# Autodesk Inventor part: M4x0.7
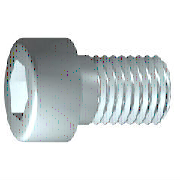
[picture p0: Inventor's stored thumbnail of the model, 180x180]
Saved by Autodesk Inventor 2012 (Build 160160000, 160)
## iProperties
Created: 2009-02
Part Number: M4x0.7
Material: 강, 연강
Description: 6각머리 태핑 나사
Document SubType Name: Modeling
Standard: KS B 1003
Standards Organization: KS
Language: ko-KR
Size Designation: M 4 x 12
Categories: <MemberInstance><Categories><Category DisplayName="조임쇠" InternalName="e4da775c-781d-43d5-af7c-5136215cf5a6" Mnemonic="FSTN"><Category DisplayName="볼트" InternalN
Density: 1 g/cm^3
Checked By: KYOUNG IL JANG
Vendor: CBT Solutions
Designer: KYOUNG IL JANG
Manager: KYOUNG IL JANG
Company: 한국ATC센터
IsCustomPart: 0
Author: KYOUNG IL JANG
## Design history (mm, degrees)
revolve "본체" stored, may be unused: angle "d10" = 90 deg
sketch "스케치2"
  geometry: L1 (0, -4.9)-(0, 4.9) reference; L2 (-4.9, 0)-(4.9, 0) reference; L3 (1.732, 0)-(0.866, -1.5); L4 (0.866, -1.5)-(-0.866, -1.5); L5 (-0.866, -1.5)-(-1.732, 0); L6 (-1.732, 0)-(-0.866, 1.5); L7 (-0.866, 1.5)-(0.866, 1.5); L8 (0.866, 1.5)-(1.732, 0); 2 further points
  constraints: 12 end point, 1 coincident, 1 horizontal alignment, 1 point on line, 12 other
extrude "슬롯" join sketch "스케치2" stored distance "d11" = 10; taper "d12" = 0 deg
workplane "Work Plane1"
fillet "Fillet2" dims "d30" = 0.1 (= R)
body "Solid1"
fillet "모깎기1" dims "d17" = 0.4 (= RR)
feature "스레드" dims "d13" = 10.25 (= GEL), "d14" = 0
chamfer "모따기1" distance "d15" = 0.42941 (= -0.5 x SPD + 0.5 x GD); stored, may be unused: second distance "d16" = 0.42941 (= GUL), angle "d27" = 45 deg
sketch "스케치1"
  geometry: L1 (-1, 0)-(12, 0); L2 (12, 0)-(12, 2); L3 (12, 2)-(1.75, 2); L4 (1.75, 2)-(1.32, 2); L5 (1.32, 2)-(0, 2); L6 (0, 2)-(0, 3.5); L7 (0, 3.5)-(-4, 3.5); L8 (-4, 3.5)-(-4, 1.732); L9 (-4, 1.732)-(-2, 1.732); L10 (-2, 1.732)-(-1, 0); L11 (-7.2, 0)-(15.2, 0) reference; L12 (0, -0.7)-(0, 4.2) reference; L13 (1.75, 2)-(0, 2)
  constraints: 22 end point, 6 parallel, 2 collinear, 2 perpendicular, 1 horizontal, 1 point on line
  dimensions: "d1" = 10.25 distance from line of L3.end L2 (= GEL); "d2" = 0.42952 distance of L4.end L3.end (computed from GAL); "d3" = 4 distance between parallel lines of L8 L6 (= KOH); "d4" = 2 distance of L8.end L9.end (= INTI); "d5" = 60 deg angle of L10 L1; "d6" = 4 diameter of L3 L1 (= GD); "d7" = 4 diameter of L5 L1 (= BDM); "d8" = 3.4641 diameter of L9 L1 (= 1.1547 x SW); "d9" = 7 diameter of L7 L1 (= KOD); "d26" = 12 distance between parallel lines of L12 L2 (= NLG)
other parameters: "GD" = 4 (= NND) [user parameter; used in 2 equation terms], "NLG" = 12 [user parameter; used in 1 equation term], "GEL" = 10.25 [user parameter; used in 2 equation terms], "KOD" = 7 [user parameter; used in 1 equation term], "KOH" = 4 [user parameter; used in 1 equation term], "INTI" = 2 [user parameter; used in 1 equation term], "GAL" = 0.42941 (= 0.61345 x PTC) [user parameter; used in 1 equation term], "GUL" = 0.42941 (= 0.61345 x PTC) [user parameter; used in 1 equation term], "BDM" = 4 (= NND) [user parameter; used in 1 equation term], "SW" = 3 [user parameter; used in 2 equation terms], "RR" = 0.4 [user parameter; used in 1 equation term], "SPD" = 3.14117 (= NND - 1.2269 x PTC) [user parameter; used in 1 equation term], "d19" = 0, "d28" = 0, "d29" = 0, "R" = 0.1 [user parameter; used in 1 equation term], "PHH" = 0.2 [user parameter], "GD1" = 3.14117 (= THREADDIA - 1.2269 x PTC) [user parameter], "THREADDIA" = 4 [user parameter; used in 1 equation term], "FAWI" = 45 deg [user parameter], "TPU" = 14.28571 (computed from PTC) [user parameter], "PTC" = 0.7 [user parameter; used in 5 equation terms], "NND" = 4 [user parameter; used in 3 equation terms], "TOA" = 30 deg [user parameter], "E0" = 3.465 (= 1.155 x SW) [user parameter]
